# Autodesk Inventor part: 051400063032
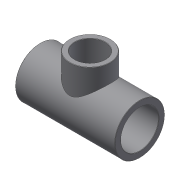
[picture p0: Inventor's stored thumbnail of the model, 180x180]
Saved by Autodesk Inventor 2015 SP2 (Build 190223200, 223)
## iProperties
Created: 2017-10
Part Number: 051400063032
Material: Generic
Description: PLASSON REDUCER TEE - CEMENT PVC 63-32-63
Document SubType Name: Modeling
Designer: KIM
Density: 1 g/cm^3
Appearance: Default
Author: KIM
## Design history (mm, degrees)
derived "051400.ipt"
feature "Solid1::051400.ipt"
feature "Solid2::051400.ipt"
tag "TaggingFeature1"
body "Solid1"
other parameters: "d0" = 144, "d1" = 77, "d2" = 38, "d4" = 63, "d5" = 56.7, "d7" = 0.63, "d8" = 38, "d9" = 56.5, "d10" = 41, "d11" = 32, "d12" = 28.8, "d23" = 22, "d24" = 0.63, "d26" = 0, "d30" = 0, "d32" = 0, "d_" = 63, "E_" = 77, "H_" = 144, "l_" = 38, "Z_" = 14, "E_1" = 41, "l_1" = 22, "Z_1" = 12.5, "H_1" = 95, "d_1" = 32
